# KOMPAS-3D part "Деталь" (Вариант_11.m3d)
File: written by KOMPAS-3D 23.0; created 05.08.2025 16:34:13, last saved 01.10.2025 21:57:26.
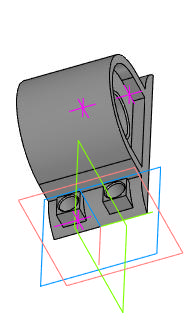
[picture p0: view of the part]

Document properties: Автор: Admin; Полное имя файла: C:\Users\ssafo\OneDrive\Desktop\ЦД_Грант\Решенные варианты\Вариант_11.m3d

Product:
- Part/product: Деталь
    Масса: 0.474568
    Форматы листов документа: A4

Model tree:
1. Эскиз:1
2. Элемент выдавливания:2
     Расстояние 1 = 20; Расстояние 2 = 20
3. Эскиз:6
4. Эскиз:7  (with: Элемент выдавливания:2)
5. Элемент выдавливания:7
     Расстояние 1 = 10
6. Эскиз:8  (with: Элемент выдавливания:7)
7. Элемент выдавливания:8
     Расстояние 2 = 10
8. Эскиз:9  (with: Элемент выдавливания:2)
9. Эскиз:10  (with: Элемент выдавливания:2)
10. Элемент выдавливания:9
     Расстояние 2 = 5
11. Эскиз:11  (with: Элемент выдавливания:9)
12. Элемент выдавливания:10
     Расстояние 2 = 15
13. Зеркальный массив:4
14. Экземпляр ( 1 )
15. Экземпляр ( 2 )  (with: Элемент выдавливания:10, Элемент выдавливания:9)
16. Фаска:7  (with: Элемент выдавливания:10)
     Угол = 30; Длина 1 = 1; Длина 2 = 0.57735
17. Фаска:8  (with: Элемент выдавливания:8)
     Угол = 45; Длина 1 = 0.5; Длина 2 = 0.5
18. Массив по точкам:1  (with: Экземпляр ( 1 ), Элемент выдавливания:7, Элемент выдавливания:8, Эскиз:8, Фаска:8)
19. Экземпляр ( 3 )  (with: Элемент выдавливания:7, Элемент выдавливания:8, Эскиз:8, Фаска:8, Экземпляр ( 2 ))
